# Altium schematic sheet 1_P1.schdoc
size 307 x 218 mm; Symbol: Drawing-Symbol_A4; Device: Drawing-Symbol_A4; @Project Name: pcbwatch; @Page Count: 1; @Update Date: 2026-05-27; @Create Date: 2026-05-20; @Schematic Name: Schematic1; @Page No: 1; @Page Name: P1; Company: EasyEDA.com; Version: V1.0; Page Size: A4; @Create Time: 13:10:33; @Update Time: 00:51:18; Width: 1170; Height: 825; Region Start: 1; X Region Count: 6; Y Region Count: 4; Blade Width: 10; Title Block Position: 3; @Board Name: Board1
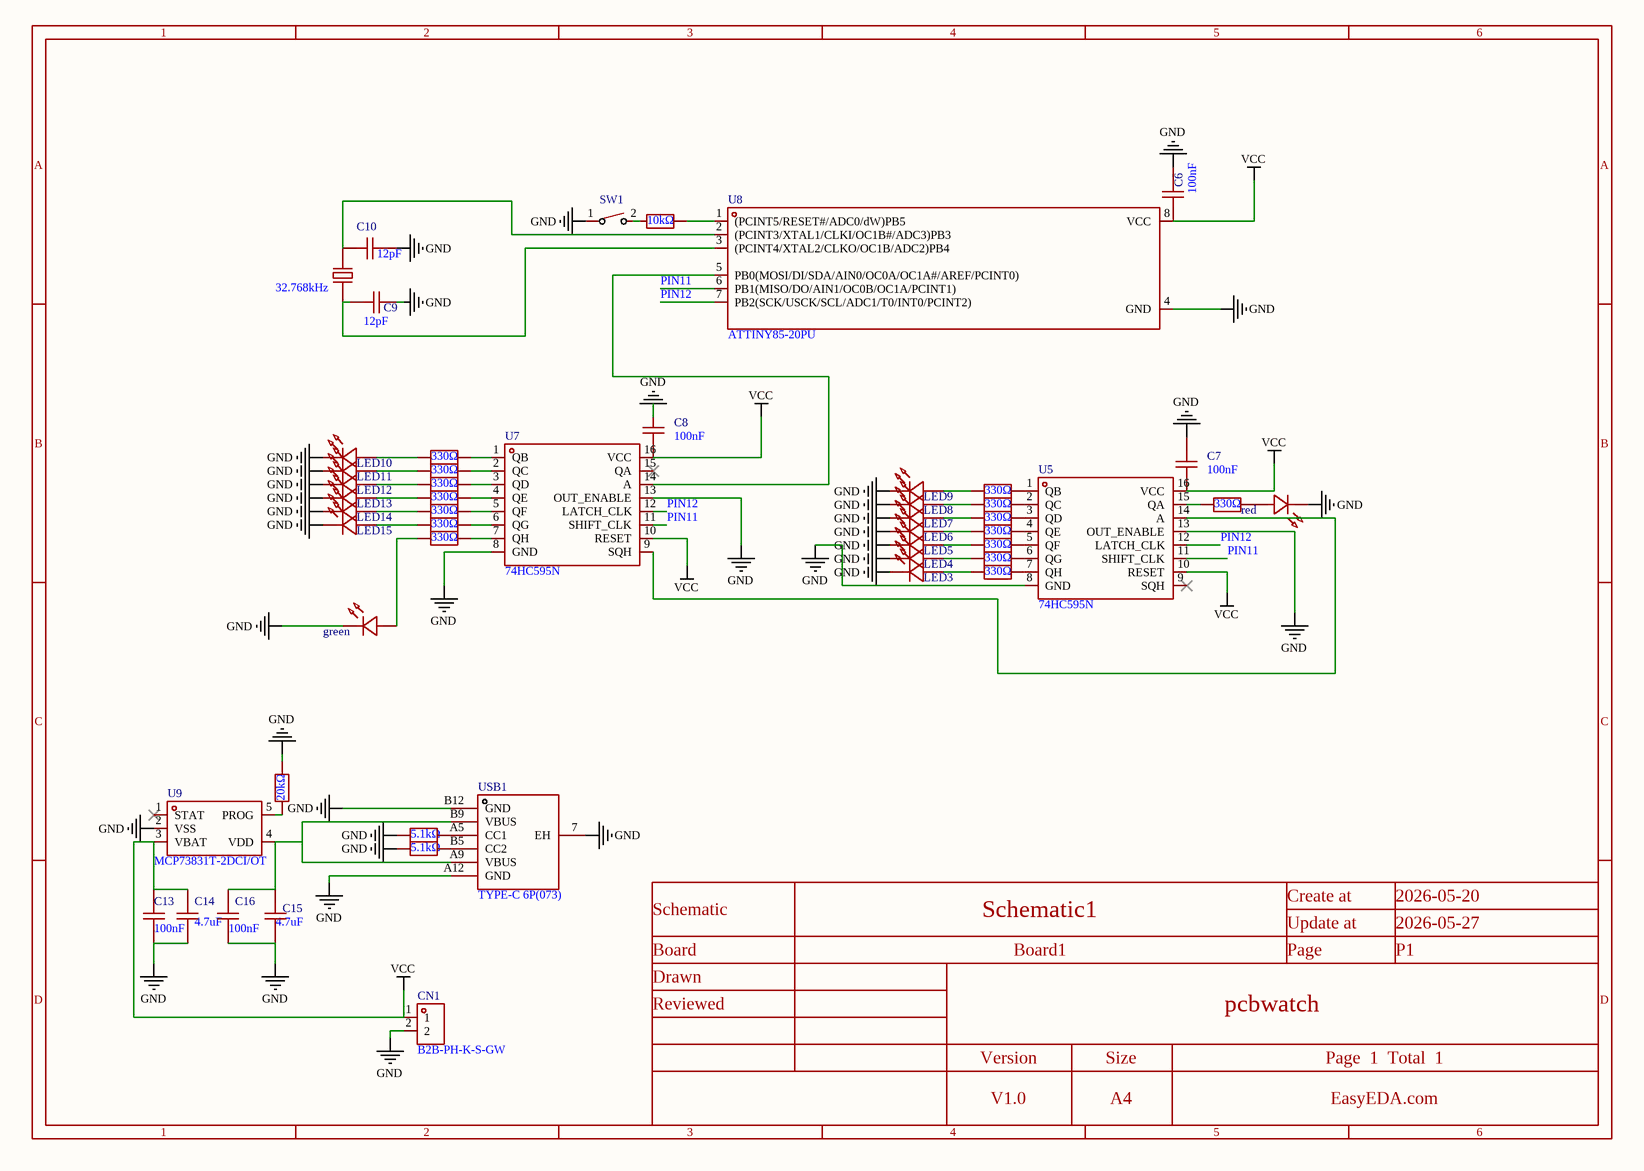
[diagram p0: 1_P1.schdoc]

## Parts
C6  100nF  [CAP-TH_L5.8-W2.4-P2.54-D0.6]
C7  100nF  [CAP-TH_L5.8-W2.4-P2.54-D0.6]
C8  100nF  [CAP-TH_L5.8-W2.4-P2.54-D0.6]
C9  12pF  [CAP-TH_L5.8-W2.4-P2.54-D0.6]
C10  12pF  [CAP-TH_L5.8-W2.4-P2.54-D0.6]
C13  100nF  [CAP-TH_L5.8-W2.4-P2.54-D0.6]
C14  4.7uF  [CAP-TH_L5.8-W2.4-P2.54-D0.6]
C15  4.7uF  [CAP-TH_L5.8-W2.4-P2.54-D0.6]
C16  100nF  [CAP-TH_L5.8-W2.4-P2.54-D0.6]
CN1  B2B-PH-K-S-GW  [CONN-TH_B2B-PH-K-S]
green  TJ-S2012EX8T5ALC2R-A5  [LED0805-RD]  (value not drawn)
LED3  TJ-S2012EX8T5ALC2R-A5  [LED0805-RD]  (value not drawn)
LED4  TJ-S2012EX8T5ALC2R-A5  [LED0805-RD]  (value not drawn)
LED5  TJ-S2012EX8T5ALC2R-A5  [LED0805-RD]  (value not drawn)
LED6  TJ-S2012EX8T5ALC2R-A5  [LED0805-RD]  (value not drawn)
LED7  TJ-S2012EX8T5ALC2R-A5  [LED0805-RD]  (value not drawn)
LED8  TJ-S2012EX8T5ALC2R-A5  [LED0805-RD]  (value not drawn)
LED9  TJ-S2012EX8T5ALC2R-A5  [LED0805-RD]  (value not drawn)
LED10  TJ-S2012EX8T5ALC2R-A5  [LED0805-RD]  (value not drawn)
LED11  TJ-S2012EX8T5ALC2R-A5  [LED0805-RD]  (value not drawn)
LED12  TJ-S2012EX8T5ALC2R-A5  [LED0805-RD]  (value not drawn)
LED13  TJ-S2012EX8T5ALC2R-A5  [LED0805-RD]  (value not drawn)
LED14  TJ-S2012EX8T5ALC2R-A5  [LED0805-RD]  (value not drawn)
LED15  TJ-S2012EX8T5ALC2R-A5  [LED0805-RD]  (value not drawn)
R20  330Ω  [RES-TH_BD2.3-L6.5-P10.50-D0.5]
R21  330Ω  [RES-TH_BD2.3-L6.5-P10.50-D0.5]
R22  330Ω  [RES-TH_BD2.3-L6.5-P10.50-D0.5]
R23  330Ω  [RES-TH_BD2.3-L6.5-P10.50-D0.5]
R24  330Ω  [RES-TH_BD2.3-L6.5-P10.50-D0.5]
R25  330Ω  [RES-TH_BD2.3-L6.5-P10.50-D0.5]
R26  330Ω  [RES-TH_BD2.3-L6.5-P10.50-D0.5]
R27  330Ω  [RES-TH_BD2.3-L6.5-P10.50-D0.5]
R28  330Ω  [RES-TH_BD2.3-L6.5-P10.50-D0.5]
R29  330Ω  [RES-TH_BD2.3-L6.5-P10.50-D0.5]
R30  330Ω  [RES-TH_BD2.3-L6.5-P10.50-D0.5]
R31  330Ω  [RES-TH_BD2.3-L6.5-P10.50-D0.5]
R32  330Ω  [RES-TH_BD2.3-L6.5-P10.50-D0.5]
R33  330Ω  [RES-TH_BD2.3-L6.5-P10.50-D0.5]
R34  330Ω  [RES-TH_BD2.3-L6.5-P10.50-D0.5]
R36  10kΩ  [RES-TH_BD2.3-L6.5-P10.50-D0.5]
R40  20kΩ  [RES-TH_BD2.3-L6.5-P10.50-D0.5]
R41  5.1kΩ  [RES-TH_BD2.3-L6.5-P10.50-D0.5]
R42  5.1kΩ  [RES-TH_BD2.3-L6.5-P10.50-D0.5]
red  TJ-S2012EX8T5ALC2R-A5  [LED0805-RD]  (value not drawn)
SW1  HX 3x4x2-2P-1.6N TACTILE SWITCH  [KEY-SMD_L4.0-W3.0-LS4.9-1]  (value not drawn)
U5  74HC595N  [DIP-16_L19.8-W6.5-P2.54-LS7.6-BL]
U7  74HC595N  [DIP-16_L19.8-W6.5-P2.54-LS7.6-BL]
U8  ATTINY85-20PU  [PDIP-8_L9.3-W6.4-P2.54-LS7.9-BL-1]
U9  MCP73831T-2DCI/OT  [SOT-23-5_L2.9-W1.6-P0.95-LS2.8-BL]
USB1  TYPE-C 6P(073)  [TYPE-C-SMD_TYPE-C-6P-073]
X1  32.768kHz  [OSC-TH_BD2.0-P0.70-D0.3]

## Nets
GND: C6.2 C7.2 C8.1 C9.1 C10.1 C13.2 C14.2 C15.2 C16.2 CN1.2 green.1(C) LED3.1(C) LED4.1(C) LED5.1(C) LED6.1(C) LED7.1(C) LED8.1(C) LED9.1(C) LED10.1(C) LED11.1(C) LED12.1(C) LED13.1(C) LED14.1(C) LED15.1(C) R40.2 R41.2 R42.2 red.1(C) SW1.1 U5.8(GND) U5.13(OUT_ENABLE) U7.8(GND) U7.13(OUT_ENABLE) U8.4(GND) U9.2(VSS) USB1.7(EH) USB1.A12(GND) USB1.B12(GND)
VCC: C6.1 C7.1 C8.2 C13.1 C14.1 CN1.1 U5.10(RESET) U5.16(VCC) U7.10(RESET) U7.16(VCC) U8.8(VCC) U9.3(VBAT)
PIN11: U5.11(SHIFT_CLK) U7.11(SHIFT_CLK) U8.6(PB1(MISO/DO/AIN1/OC0B/OC1A/PCINT1))
PIN12: U5.12(LATCH_CLK) U7.12(LATCH_CLK) U8.7(PB2(SCK/USCK/SCL/ADC1/T0/INT0/PCINT2))
NetC9_2: C9.2 U8.3((PCINT4/XTAL2/CLKO/OC1B/ADC2)PB4) X1.1
NetC10_2: C10.2 U8.2((PCINT3/XTAL1/CLKI/OC1B#/ADC3)PB3) X1.2
NetC15_1: C15.1 C16.1 U9.4(VDD) USB1.A9(VBUS) USB1.B9(VBUS)
Netgreen_2: green.2(A) R26.1
NetLED3_2: LED3.2(A) R33.1
NetLED4_2: LED4.2(A) R32.1
NetLED5_2: LED5.2(A) R31.1
NetLED6_2: LED6.2(A) R30.1
NetLED7_2: LED7.2(A) R29.1
NetLED8_2: LED8.2(A) R28.1
NetLED9_2: LED9.2(A) R27.1
NetLED10_2: LED10.2(A) R20.1
NetLED11_2: LED11.2(A) R21.1
NetLED12_2: LED12.2(A) R22.1
NetLED13_2: LED13.2(A) R23.1
NetLED14_2: LED14.2(A) R24.1
NetLED15_2: LED15.2(A) R25.1
NetR20_2: R20.2 U7.1(QB)
NetR21_2: R21.2 U7.2(QC)
NetR22_2: R22.2 U7.3(QD)
NetR23_2: R23.2 U7.4(QE)
NetR24_2: R24.2 U7.5(QF)
NetR25_2: R25.2 U7.6(QG)
NetR26_2: R26.2 U7.7(QH)
NetR27_2: R27.2 U5.1(QB)
NetR28_2: R28.2 U5.2(QC)
NetR29_2: R29.2 U5.3(QD)
NetR30_2: R30.2 U5.4(QE)
NetR31_2: R31.2 U5.5(QF)
NetR32_2: R32.2 U5.6(QG)
NetR33_2: R33.2 U5.7(QH)
NetR34_1: R34.1 U5.15(QA)
NetR34_2: R34.2 red.2(A)
NetR36_1: R36.1 SW1.2
NetR36_2: R36.2 U8.1((PCINT5/RESET#/ADC0/dW)PB5)
NetR40_1: R40.1 U9.5(PROG)
NetR41_1: R41.1 USB1.A5(CC1)
NetR42_1: R42.1 USB1.B5(CC2)
NetU5_14: U5.14(A) U7.9(SQH)
NetU7_14: U7.14(A) U8.5(PB0(MOSI/DI/SDA/AIN0/OC0A/OC1A#/AREF/PCINT0))

Not connected (* = marked no-connect by the designer): U5 9(SQH)*; U7 15(QA)*; U9 1(STAT)*

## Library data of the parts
C6-C10 C13-C16 = CC1H104ZA1ED3F5P1100: Manufacturer: Dersonic(德尔创); Add into BOM: yes; Tolerance: -20%~+80%; Voltage Rating: 50V; Pin Spacing: 2.54mm; Temperature Coefficient: Y5V; Body Thickness: 2.4mm
CN1 = B2B-PH-K-S-GW: Manufacturer: JST; Add into BOM: yes; Pins Structure: 1x2P; Pitch: 2mm; Reference Series: PH; Number of PINs Per Row: 2; Current Rating: 2A; Voltage Rating: 100V; Plastic Material: PA66; Flame Retardant Rating: UL94V-0; Supplementary Features: K Pin; Z-Height of the Board: 6mm; X-Length of Bottom Edge on Board (Spacing Line): 5.9mm; Y-Width of Bottom Edge on Board: 4.5mm
green LED3-LED15 red = TJ-S2012EX8T5ALC2R-A5: Manufacturer: TOGIALED(统佳); Add into BOM: yes; Lamp Holder Type: 2mm x 1.25mm square LED; Illumination Color: Red; Voltage - Forward(Vf): 1.8V~2.4V; Power(Watts): 48mW; Forward Current: 20mA; Wavelength - Dominant: 620nm~630nm; Peak Wavelength: 631nm; Diode Configuration: Discrete Diode; Lens Color: Water Clear; Luminous Intensity: 200mcd; Viewing Angle: 120°
R20-R34 R36 R40-R42 = MF1/4W-1KΩ±1%T52: Manufacturer: 华星机电; Add into BOM: yes; Tolerance: ±1%; Power(Watts): 250mW; Temperature Coefficient: ±200ppm/℃
SW1 = HX 3x4x2-2P-1.6N TACTILE SWITCH: Manufacturer: hanxia(韩下); Add into BOM: yes; Circuit: SPST; Actuator Style: Round Button; Operating Force: 1.6N; Switch Height: 2mm; with Bracket: Without Bracket; Contact Current: 50mA; Voltage Rating: 12V; Actuator/Cap Color: Black; With Lamp: No; Life: 100,000 Cycles
U5 U7 = 74HC595N: Manufacturer: HTC; Symbol: 74HC595N_C669328; Add into BOM: yes; Function: Serial-to-Serial or Parallel; Voltage - Supply: 2V~6V; Clock Frequency: 28MHz; Number of Elements: 1; Number of Bits per Element: 8; Output Type: Tri-State
U8 = ATTINY85-20PU: Manufacturer: MICROCHIP(美国微芯); Add into BOM: yes; CPU Core: AVR; CPU Maximum Speed: 20MHz; Core Size: 8 Bit; Program Storage Size: 8KB; Program Memory Type: FLASH; RAM Size: 512Byte; Number of I/O: 6; ADC (Bit): 10bit; Oscillator Type: Built-in; Voltage - Supply: 2.7V~5.5V
U9 = MCP73831T-2DCI/OT: Manufacturer: MICROCHIP(美国微芯); Add into BOM: yes; The Chip Type: Charging IC; Voltage - Supply: 3.75V~6V; Charge Current - Max: 550mA; Charging Saturation Voltage: 4.2V; Type of Battery: Lithium Battery; Number of Cells: 1; Battery Temperature Detection: Not supported; Supply Current (Iq): 53uA
USB1 = TYPE-C 6P(073): Manufacturer: SHOU HAN(首韩); Add into BOM: yes; Gender: Female; Number of Ports: 1; Current Rating-Power: 3A; Voltage Rating: 5V; Connect-Disconnect Life: 10,000 Cycles; Detection color: Black
X1 = TAXD32768K2BGBBZT2S: Manufacturer: YJX(雅晶鑫); Add into BOM: yes; Normal temperature Frequency Tolerance: ±10ppm; Load Capacitance: 12.5pF; Frequency Stability: ±20ppm; Equivalent Series Resistance(ESR): 40kΩ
